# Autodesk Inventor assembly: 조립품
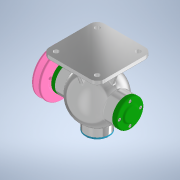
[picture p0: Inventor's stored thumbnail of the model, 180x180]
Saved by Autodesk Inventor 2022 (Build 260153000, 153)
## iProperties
Created: 2024-04
Part Number: 조립품
Document SubType Name: Assembly
Designer: user
Author: user
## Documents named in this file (16)
- C:\Users\user\Desktop\740406V1009\조립품.iam
- C:\Users\user\Desktop\740406V1009\본체.ipt
- C:\Users\user\Desktop\740406V1009\뒤커버.ipt
- C:\Users\user\Desktop\740406V1009\앞커버.ipt
- C:\Users\user\Desktop\740406V1009\상부커버.ipt
- C:\Users\user\Desktop\740406V1009\베어링- 6202.ipt
- KS B 2023 - 6202 - 15 x 35 x 11 - 7.8.ipt
- C:\Users\user\Desktop\740406V1009\칼라.ipt
- C:\Users\user\Desktop\740406V1009\편심축.ipt
- C:\Users\user\Desktop\740406V1009\키 4 x 4 x 12.ipt
- C:\Users\user\Desktop\740406V1009\오일실 15 30 7.ipt
- C:\Users\user\Desktop\740406V1009\V-벨트풀리.ipt
- C:\Users\user\Desktop\740406V1009\너트 M8.ipt
- C:\Users\user\Desktop\740406V1009\볼트 M4 x 16.ipt
- C:\Users\user\Desktop\740406V1009\볼트 M4 x 12.ipt
- C:\Users\user\Desktop\740406V1009\슬라이드.ipt
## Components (15 placed, 4 different names)
1. KS B 2023 - 6202 - 15 x 35 x 11 - 7.8:1
2. KS B 2023 - 6202 - 15 x 35 x 11 - 7.8:2
3. V-벨트풀리:1
4. ISO 4762 M4 x 16:1
5. ISO 4762 M4 x 16:2
6. ISO 4762 M4 x 16:3
7. ISO 4762 M4 x 16:4
8. ISO 4762 M4 x 16:5
9. ISO 4762 M4 x 16:6
10. ISO 4762 M4 x 16:7
11. ISO 4762 M4 x 16:8
12. KS B 1021 - 에 따름 ISO 1207 - 미터 A  M 4 x 12:1
13. KS B 1021 - 에 따름 ISO 1207 - 미터 A  M 4 x 12:2
14. KS B 1021 - 에 따름 ISO 1207 - 미터 A  M 4 x 12:3
15. KS B 1021 - 에 따름 ISO 1207 - 미터 A  M 4 x 12:4
